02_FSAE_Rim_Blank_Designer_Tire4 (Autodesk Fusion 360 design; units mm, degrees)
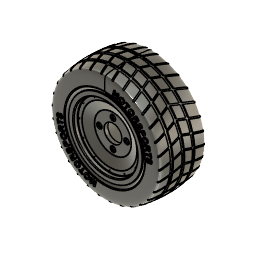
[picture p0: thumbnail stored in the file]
part number: 2026-07-27-09-56-27-671
sketch "Sketch1" plane through (0, 0, 0) normal (1, 0, 0) x axis (0, 1, 0)
  line L1 (153.5, 0) -> (0, 0)
  line L2 (0, 119.5) -> (0, 104)
  line L3 (143.5, 124.5) -> (5, 124.5)
  line L4 (148.5, 134.75) -> (148.5, 129.5)
  line L5 (153.5, 138.25) -> (152, 138.25)
  line L6 (2.5, 119.5) -> (2.5, 104)
  line L7 (143.5, 122) -> (5, 122)
  line L8 (151, 134.75) -> (151, 129.5)
  line L9 (153.5, 135.75) -> (152, 135.75)
  line L10 (2.5, 104) -> (0, 104)
  line L11 (153.5, 135.75) -> (153.5, 138.25)
  arc A1 centre (152, 134.75) radius 3.5 clockwise from (148.5, 134.75) to (152, 138.25)
  arc A2 centre (143.5, 129.5) radius 5 clockwise from (148.5, 129.5) to (143.5, 124.5)
  arc A3 centre (5, 119.5) radius 5 clockwise from (0, 119.5) to (5, 124.5)
  arc A4 centre (5, 119.5) radius 2.5 clockwise from (2.5, 119.5) to (5, 122)
  arc A5 centre (143.5, 129.5) radius 7.5 clockwise from (151, 129.5) to (143.5, 122)
  arc A6 centre (152, 134.75) radius 1 clockwise from (151, 134.75) to (152, 135.75)
  point P1 (0, 0)
  point P2 (0, 0)
  point P4 (0, 104)
  point P3 (153.5, 0)
  point P7 (153.5, 138.25)
  point P6 (148.5, 124.5)
  point P5 (0, 124.5)
  coincident P1 P2
  horizontal L1
  perpendicular L1 L2
  perpendicular L2 L3
  perpendicular L3 L4
  perpendicular L4 L5
  vertical P1 P4
  vertical P3 P7
  tangent L4 A1
  tangent L5 A1
  coincident P6 L3
  coincident P6 L4
  tangent L3 A2
  tangent L4 A2
  coincident P5 L2
  coincident P5 L3
  tangent L2 A3
  tangent L3 A3
  equal A2 A3
  perpendicular L6 L10
  perpendicular L9 L11
  dimension "d1" distance P2 P3 = 153.5
  dimension "d2" = 208
  dimension "d3" = 249
  dimension "d4" = 276.5
  dimension "d5" distance P5 P6 = 148.5
  dimension "d6" radius A1 = 3.5
  dimension "d7" radius A2 = 5
  dimension "d8" = 2.5
revolve "Revolve1" sketch "Sketch1" AlongAngle 360 bodies "FSAE Rim Back"
sketch "Sketch2" plane through (0, 0, 0) normal (0, -1, 0) x axis (1, 0, 0)
  circle C1 centre (0, 0) radius 104
  circle C2 centre (0, 0) radius 119.5
  circle C3 centre (0, 0) radius 112
  circle C4 centre (0, 112) radius 2.15
  point P1 (0, 0)
  point P3 (0, 0)
  point P4 (0, 112)
  coincident P1 P3
  coincident C3 P4
  vertical P3 P4
  dimension "d10" diameter C3 = 224
  dimension "d11" diameter C4 = 4.3
extrude "Extrude1" cut sketch "Sketch2" profile of C4 to an object
circular_pattern "C-Pattern1" TotalAngle 360
canvas "Canvas1"
move "Move1"
sketch "Sketch4" plane through (0, 0, 0) normal (1, 0, 0) x axis (0, 1, 0)
  line L1 (14, 0) -> (0, 0)
  line L2 (14, 72.5) -> (14, 0)
  line L3 (-8, 102.5) -> (14, 72.5)
  line L4 (-8, 124.5) -> (-8, 102.5)
  line L5 (-23.5, 124.5) -> (-8, 124.5)
  line L6 (-23.5, 138) -> (-23.5, 124.5)
  line L7 (-28.25, 138) -> (-23.5, 138)
  line L8 (-28.25, 0) -> (-28.25, 138)
  line L9 (0, 0) -> (-28.25, 0)
  line L10 (-13, 118.1658) -> (-28.25, 119.5)
  line L11 (-13, 102.5) -> (-13, 118.1658)
  line L12 (0, 68.6338) -> (-13, 102.5)
  line L13 (0, 0) -> (0, 68.6338)
  point P1 (0, 0)
  point P2 (0, 0)
  point P11 (0, 0)
  point P12 (-28.25, 119.5)
  point P5 (-8, 102.5)
  point P14 (-13, 102.5)
  point P3 (14, 0)
  point P4 (14, 72.5)
  point P6 (-8, 124.5)
  point P8 (-23.5, 138)
  point P9 (-28.25, 138)
  coincident P1 P2
  horizontal L1
  perpendicular L1 L2
  perpendicular L1 L4
  perpendicular L4 L5
  perpendicular L5 L6
  perpendicular L6 L7
  coincident P1 P11
  collinear L1 L9
  perpendicular L8 L9
  coincident L8 P12
  parallel L8 L11
  vertical L13
  horizontal P5 P14
  dimension "d29" distance P2 P3 = 14
  dimension "d30" = 145
  dimension "d31" = 205
  dimension "d32" = 249
  dimension "d33" = 276
  dimension "d34" distance P4 P6 = 22
  dimension "d35" distance P6 P8 = 15.5
  dimension "d36" distance P8 P9 = 4.75
  dimension "d37" distance L4 L11 = 5
  dimension "d38" angle L12 L13 = 159
  dimension "d39" angle L10 L11 = 95
  dimension "d40" = 239
revolve "Revolve3" sketch "Sketch4" AlongAngle 360 bodies "FSAE Rim Front"
sketch "Sketch5" plane through (0, 0, 0) normal (0, -1, 0) x axis (1, 0, 0)
  circle C1 centre (0, 0) radius 68.6338
  circle C2 centre (0, 0) radius 33
  point P1 (0, 0)
  point P3 (0, 0)
  coincident P1 P3
  dimension "d42" diameter C2 = 66
extrude "Extrude2" cut sketch "Sketch5" profile of C2 to an object
sketch "Sketch6" plane through (0, 0, 0) normal (0, -1, 0) x axis (1, 0, 0)
  circle C1 centre (0, 0) radius 33
  circle C2 centre (0, 0) radius 68.6338
  circle C3 centre (0, 0) radius 50.8
  point P1 (0, 0)
  point P4 (0, 0)
  point P3 (0, 50.8)
  coincident P1 P4
  coincident P3 C3
  vertical P1 P3
  dimension "d45" diameter C3 = 101.6
hole "Hole1" HoleDiameter 10.5 TipAngle 180 CBDepth 5 CBDiameter 20
chamfer "Chamfer2" sketch "Sketch1" distance 0.5
circular_pattern "C-Pattern2" TotalAngle 360
sketch "Sketch7" plane through (0, -13, 0) normal (0, -1, 0) x axis (1, 0, 0)
  circle C1 centre (0, 0) radius 102.5
  circle C2 centre (0, 0) radius 118.1658
  circle C3 centre (0, 0) radius 112
  point P1 (0, 0)
  point P3 (0, 0)
  point P4 (0, 112)
  coincident P1 P3
  coincident C3 P4
  vertical P1 P4
  dimension "d53" diameter C3 = 224
hole "Hole2" HoleDiameter 4.3 TipAngle 180
circular_pattern "C-Pattern3" TotalAngle 360
fillet "Fillet1" radius 1 3 2
chamfer "Chamfer1" distance 0.5
form "Form1" bodies "Tire"
fillet "Fillet2" radius 5
sketch "Sketch8" plane through (0, 0, 0) normal (1, 0, 0) x axis (0, 1, 0)
  line L1 (47.5, 224.911) -> (47.5, 204.911)
  line L2 (57.5, 224.911) -> (47.5, 224.911)
  line L3 (57.5, 204.9943) -> (57.5, 224.911)
  line L4 (87.5, 224.911) -> (87.5, 204.2438)
  line L5 (97.5, 224.911) -> (87.5, 224.911)
  line L6 (97.5, 203.6595) -> (97.5, 224.911)
  line L7 (17.5, 224.911) -> (17.5, 203.6595)
  line L8 (7.5, 224.911) -> (17.5, 224.911)
  line L9 (7.5, 202.9073) -> (7.5, 224.911)
  arc A1 centre (57.5, -395.0057) radius 600 clockwise from (-46, 196) to (161, 196)
  point P2 (-46, 196)
  point P3 (161, 196)
  point P8 (57.5, 204.9943)
  point P9 (87.5, 204.2438)
  point P12 (97.5, 203.6595)
  point P13 (17.5, 203.6595)
  point P16 (7.5, 202.9073)
  point P5 (47.5, 204.911)
  point P1 (0, 0)
  point P6 (47.5, 224.911)
  point P7 (57.5, 224.911)
  horizontal P2 P3
  vertical L1
  perpendicular L1 L2
  midpoint A1 P8
  perpendicular L2 L3
  coincident A1 P9
  parallel L3 L4
  perpendicular L4 L5
  coincident A1 P12
  perpendicular L5 L6
  coincident A1 P13
  perpendicular L5 L7
  perpendicular L7 L8
  coincident A1 P16
  perpendicular L8 L9
  collinear L2 L8
  collinear L2 L5
  equal L2 L8
  equal L2 L5
  coincident A1 P5
  dimension "d68" radius A1 = 600
  dimension "d69" distance P1 P3 = 196
  dimension "d70" distance P1 P2 = 46
  dimension "d71" distance P1 P3 = 161
  dimension "d73" distance P6 P7 = 10
  dimension "d74" distance L1 L7 = 30
  dimension "d75" distance L3 L4 = 30
  dimension "d76" distance P5 P6 = 20
revolve "Revolve4" AlongAngle 360
revolve "Revolve5" sketch "Sketch8" AlongAngle 360
work_plane "WorkPlane1" AlongDistance 275 ExtraOffset 0
sketch "Sketch9" plane through (0, 0, 275) normal (0, 0, 1) x axis (1, 0, 0)
  line L1 (-48.7008, 53.5011) -> (0, -75.7953)
  line L2 (0, 197.5142) -> (-48.7008, 53.5011)
  line L3 (-43.392, 53.5917) -> (4.6791, -74.0329)
  line L4 (4.7365, 195.9124) -> (-43.392, 53.5917)
  line L5 (4.6791, -74.0329) -> (0, -75.7953)
  line L6 (0, 197.5142) -> (4.7365, 195.9124)
  perpendicular L3 L5
  perpendicular L2 L6
  dimension "d80" = 5
step "SurfaceExtend" extendDistance 125
extrude "Extrude3" cut sketch "Sketch9" to an object
circular_pattern "C-Pattern4" countU 30 TotalAngle 360
remove_body "RemoveBody1"
remove_body "RemoveBody2"
work_plane "WorkPlane2" AlongDistance -150 ExtraOffset 0
sketch "Sketch10" plane through (0, -150, 0) normal (0, 1, 0) x axis (1, 0, 0)
  circle C1 centre (0, 0) radius 157.5
  point P1 (0, 0)
  point P2 (0, 0)
  coincident P1 P2
  dimension "d88" diameter C1 = 315
  dimension "d89" Text1-Height = 20
extrude "Extrude4" sketch "Sketch10" blind 2
circular_pattern "C-Pattern5" TotalAngle 360
named bodies: "FSAE Rim Back", "FSAE Rim Front", "Tire"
